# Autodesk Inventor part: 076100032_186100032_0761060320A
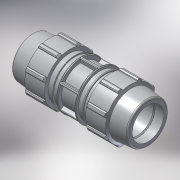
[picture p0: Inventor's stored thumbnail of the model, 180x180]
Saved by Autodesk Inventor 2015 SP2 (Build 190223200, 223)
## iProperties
Created: 2017-02
Part Number: 076100032_186100032_0761060320A
Material: PVC-Piping
Description: PLASSON REPAIR COUPLER 32
Document SubType Name: Modeling
Designer: KIM
Mass: 8658.36 g
Surface Area: 5623.3 cm^2
Volume: 6184.54 cm^3
Density: 1.4 g/cm^3
Appearance: Smooth - White
Author: KIM
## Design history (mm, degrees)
derived "07610.ipt"
feature "Solid1::07610.ipt"
tag "TaggingFeature1"
body "Solid1"
other parameters: "d1" = 174, "d2" = 32, "d4" = 14.5, "d5" = 24.85714, "d7" = 64, "d8" = 48, "d9" = 24.85714, "d11" = 3.48571, "d12" = 51.2, "d13" = 120 deg, "d14" = 48, "d15" = 10 deg, "d16" = 57.6, "d18" = 1.6, "d19" = 35 deg, "d20" = 17.5 deg, "d21" = 59.52, "d23" = 0, "d25" = 360 deg, "d27" = 1.28, "d33" = 0.64, "d34" = 3.2, "d36" = 0, "d37" = 0.64, "d38" = 0.64, "d40" = 360 deg, "d42" = 31.32, "d43" = 1.92, "d46" = 0.96, "d50" = 6.21143, "d51" = 51.2, "d_" = 32, "E_" = 64, "H_" = 174, "d49" = 15.90857
